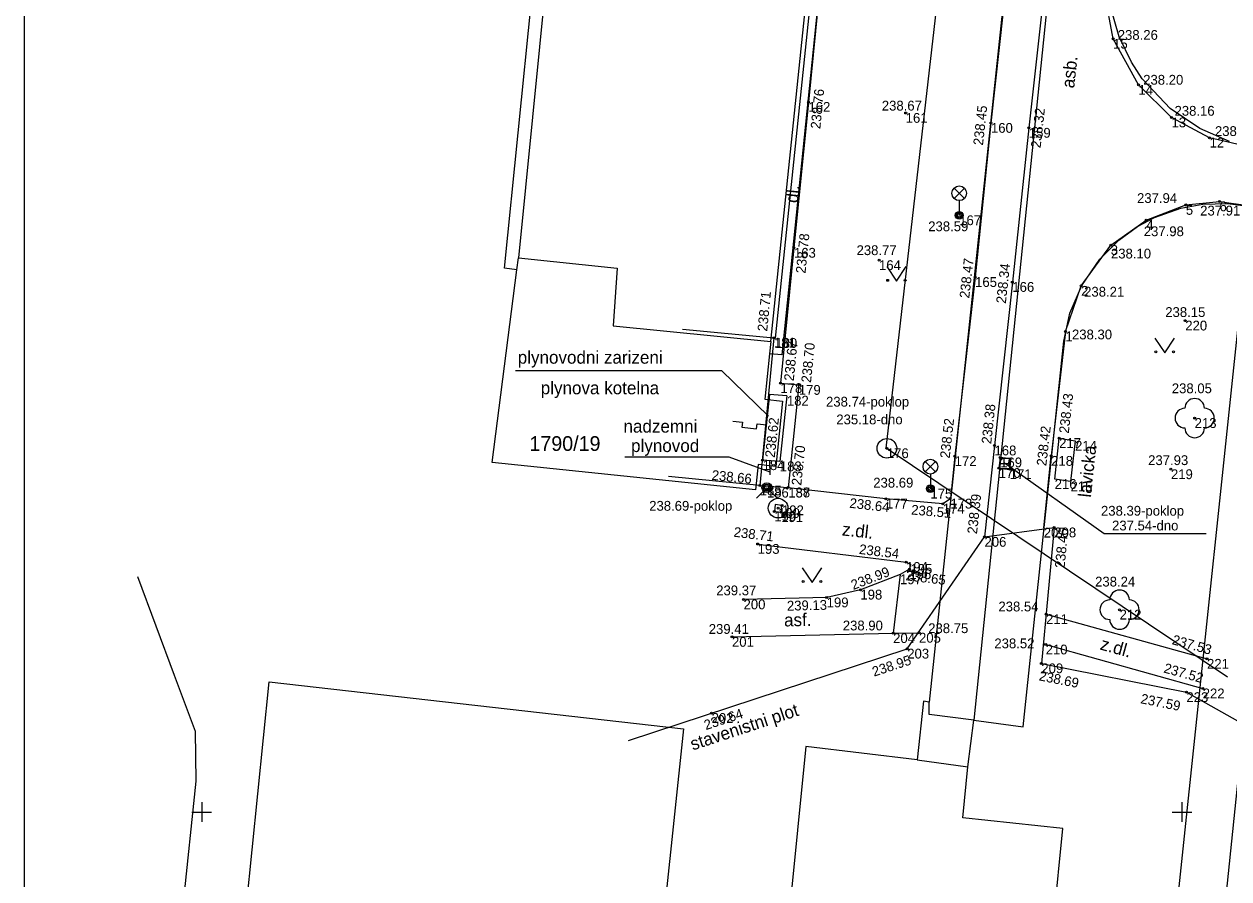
# Model space of a CAD drawing. Extents: x -596309 to -596099, y -1158697 to -1158513.
# Drawn here: x -596309.1 to -596247.6, y -1158653.4 to -1158609.8 of the extents above; entities that cross this region are included whole.
import ezdxf

# ---------------------------------------------------------------- set-up
doc = ezdxf.new("R2010")
doc.units = 0
for name, color, linetype in [('Vrstva 1', 7, 'Continuous'), ('Vrstva 10', 7, 'Continuous'), ('Vrstva 11', 7, 'Continuous'), ('Vrstva 14', 7, 'Continuous'), ('Vrstva 2', 7, 'Continuous'), ('Vrstva 22', 7, 'Continuous'), ('Vrstva 27', 7, 'Continuous'), ('Vrstva 3', 7, 'Continuous'), ('Vrstva 31', 7, 'Continuous'), ('Vrstva 32', 7, 'Continuous'), ('Vrstva 33', 7, 'Continuous'), ('Vrstva 36', 7, 'Continuous'), ('Vrstva 40', 7, 'Continuous'), ('Vrstva 5', 7, 'Continuous'), ('Vrstva 51', 7, 'Continuous'), ('Vrstva 58', 7, 'Continuous'), ('Vrstva 59', 7, 'Continuous'), ('Vrstva 60', 7, 'Continuous'), ('Vrstva 61', 7, 'Continuous'), ('Vrstva 63', 7, 'Continuous'), ('Vrstva 7', 7, 'Continuous')]:
    doc.layers.add(name, color=color, linetype=linetype)

msp = doc.modelspace()

# ---------------------------------------------------------------- linework, layer by layer
at = {"layer": 'Vrstva 1'}
for p, q in [((-596284.56, -1158622.27), (-596277.87, -1158556.03)), ((-596252.59, -1158566.74), (-596260.61, -1158645.31)), ((-596268.11, -1158604.33), (-596270.4, -1158626.69)), ((-596258.77, -1158605.41), (-596262.89, -1158644.39)), ((-596253.2, -1158610.47), (-596253.61, -1158609.06)), ((-596252.57, -1158611.75), (-596253.2, -1158610.47)), ((-596252.02, -1158612.6), (-596252.57, -1158611.75)), ((-596250.6, -1158614.12), (-596252.02, -1158612.6)), ((-596249.08, -1158615.14), (-596250.6, -1158614.12)), ((-596247.57, -1158615.8), (-596249.08, -1158615.14)), ((-596253.81, -1158688.53), (-596246.48, -1158619.11)), ((-596251.4, -1158619.68), (-596250.05, -1158619.21)), ((-596250.05, -1158619.21), (-596248.94, -1158619)), ((-596248.94, -1158619), (-596247.67, -1158618.96)), ((-596247.67, -1158618.96), (-596246.48, -1158619.11)), ((-596252.26, -1158620.14), (-596251.4, -1158619.68)), ((-596244.17, -1158619.38), (-596252.171, -1158697)), ((-596253.22, -1158620.84), (-596252.26, -1158620.14)), ((-596254.18, -1158621.8), (-596253.22, -1158620.84)), ((-596255.11, -1158623.15), (-596254.18, -1158621.8)), ((-596283.92, -1158622.34), (-596284.56, -1158622.27)), ((-596255.71, -1158624.56), (-596255.11, -1158623.15)), ((-596256.02, -1158625.99), (-596255.71, -1158624.56)), ((-596258.09, -1158645.65), (-596256.02, -1158625.99)), ((-596270.4, -1158626.69), (-596271.03, -1158626.63)), ((-596303.27, -1158637.985), (-596301.41, -1158643.02)), ((-596301.41, -1158643.02), (-596300.34, -1158645.87)), ((-596300.63, -1158683.35), (-596296.56, -1158643.35)), ((-596296.56, -1158643.35), (-596275.42, -1158645.75)), ((-596275.42, -1158645.75), (-596279.26, -1158682.13)), ((-596260.61, -1158645.31), (-596258.09, -1158645.65)), ((-596300.34, -1158645.87), (-596300.3, -1158648.42)), ((-596263.5, -1158647.34), (-596260.92, -1158647.69)), ((-596300.3, -1158648.42), (-596303.27, -1158677.086))]:
    msp.add_line(p, q, dxfattribs=at)
for points in [[(-596270.97, -1158626.01), (-596268.7, -1158604.18), (-596268.05, -1158598.2), (-596264.37, -1158561.26), (-596268.27, -1158560.79), (-596268.03, -1158558.14), (-596277.39, -1158556.98), (-596283.84, -1158621.73)], [(-596270.97, -1158626.01), (-596271.03, -1158626.63), (-596271.27, -1158628.94), (-596270.38, -1158629.04), (-596270.72, -1158632.37), (-596271.62, -1158632.28), (-596271.75, -1158633.57), (-596285.18, -1158632.17), (-596283.92, -1158622.34), (-596283.84, -1158621.73)], [(-596283.84, -1158621.73), (-596278.81, -1158622.27), (-596279.01, -1158625.2), (-596270.97, -1158626.01)], [(-596260.653, -1158697), (-596259.75, -1158687.83), (-596256.08, -1158650.83), (-596261.18, -1158650.29), (-596260.92, -1158647.69), (-596260.61, -1158645.31), (-596262.9, -1158645.02), (-596262.89, -1158644.39), (-596263.19, -1158644.35), (-596263.5, -1158647.34)], [(-596263.5, -1158647.34), (-596269.19, -1158646.65), (-596274.198, -1158697)]]:
    msp.add_lwpolyline(points, dxfattribs=at)
at = {"layer": 'Vrstva 10'}
for p in [(-596255.94, -1158625.49), (-596257.05, -1158635.5)]:
    msp.add_line(p, (-596256.67, -1158631.84), dxfattribs=at)
for points in [[(-596255.23, -1158545.06), (-596254.2, -1158547.01), (-596253.17, -1158550.76), (-596252.36, -1158555.01), (-596251.99, -1158558.97), (-596251.94, -1158561.36), (-596252.44, -1158566.04), (-596253.24, -1158573.57), (-596254.4, -1158584.31), (-596255.5, -1158594.13), (-596256.77, -1158605.75), (-596257.81, -1158615.11), (-596258.65, -1158622.97), (-596259.56, -1158631.31), (-596260.07, -1158635.97)], [(-596255.94, -1158625.49), (-596255.14, -1158623.17), (-596253.63, -1158621.09), (-596251.82, -1158619.81), (-596249.8, -1158619.04), (-596248.08, -1158618.86), (-596246.63, -1158619.07), (-596246.32, -1158616.14), (-596248.59, -1158615.61), (-596250.53, -1158614.58), (-596252.22, -1158612.92), (-596253.51, -1158610.57), (-596253.93, -1158608.27)]]:
    msp.add_lwpolyline(points, dxfattribs=at)
at = {"layer": 'Vrstva 11'}
for p, q in [((-596271.53, -1158633.35), (-596270.08, -1158633.45)), ((-596264.38, -1158637.88), (-596264.73, -1158640.88)), ((-596256.93, -1158639.91), (-596248.72, -1158642.19)), ((-596256.95, -1158641.46), (-596248.94, -1158643.7))]:
    msp.add_line(p, q, dxfattribs=at)
for points in [[(-596268.09, -1158604.13), (-596269.05, -1158613.79), (-596269.79, -1158621.23), (-596270.48, -1158628.13), (-596269.54, -1158628.22), (-596270.08, -1158633.46)], [(-596268.09, -1158604.13), (-596264.04, -1158604.57), (-596258.68, -1158605.13), (-596259.74, -1158614.86), (-596260.55, -1158622.72), (-596261.59, -1158631.85), (-596261.81, -1158634.02), (-596262.2, -1158634.28), (-596265.1, -1158634.02), (-596270.08, -1158633.46)], [(-596271.64, -1158636.33), (-596264.07, -1158637.25), (-596263.85, -1158637.35), (-596263.9, -1158637.62), (-596264.38, -1158637.88), (-596266.4, -1158638.66), (-596268.12, -1158639.06), (-596272.36, -1158639.16)], [(-596272.95, -1158641.07), (-596264.73, -1158640.88), (-596263.41, -1158640.86)]]:
    msp.add_lwpolyline(points, dxfattribs=at)
msp.add_lwpolyline([(-596255.45, -1158631.07), (-596255.68, -1158633.14), (-596256.49, -1158633.02), (-596256.26, -1158630.93)], close=True, dxfattribs=at)
at = {"layer": 'Vrstva 2'}
msp.add_lwpolyline([(-596248.77, -1158635.814), (-596253.967, -1158635.814), (-596259.048, -1158632.215)], dxfattribs=at)
for centre in [(-596253.51, -1158610.57), (-596252.22, -1158612.92), (-596269.05, -1158613.79), (-596264.09, -1158614.35), (-596259.74, -1158614.86), (-596250.53, -1158614.58), (-596257.81, -1158615.11), (-596248.59, -1158615.61), (-596249.8, -1158619.04), (-596248.08, -1158618.86), (-596251.82, -1158619.81), (-596269.79, -1158621.23), (-596253.63, -1158621.09), (-596265.45, -1158621.86), (-596260.55, -1158622.72), (-596258.65, -1158622.97), (-596255.14, -1158623.17), (-596249.83, -1158624.94), (-596255.94, -1158625.49), (-596270.81, -1158625.81), (-596270.48, -1158628.13), (-596269.54, -1158628.22), (-596249.35, -1158629.91), (-596256.26, -1158630.93), (-596265.05, -1158631.45), (-596259.56, -1158631.31), (-596271.39, -1158632.06), (-596261.59, -1158631.85), (-596259.27, -1158631.92), (-596256.67, -1158631.84), (-596259.34, -1158632.46), (-596258.78, -1158632.52), (-596250.56, -1158632.52), (-596271.53, -1158633.35), (-596270.08, -1158633.45), (-596265.1, -1158634.02), (-596270.79, -1158634.67), (-596270.6, -1158634.5), (-596270.44, -1158634.71), (-596270.4, -1158634.36), (-596262.2, -1158634.28), (-596260.07, -1158635.97), (-596256.51, -1158635.49), (-596271.64, -1158636.33), (-596264.07, -1158637.25), (-596263.9, -1158637.62), (-596268.12, -1158639.06), (-596266.4, -1158638.66), (-596272.36, -1158639.16), (-596253.18, -1158639.68), (-596256.93, -1158639.91), (-596264.73, -1158640.88), (-596263.41, -1158640.86), (-596272.95, -1158641.07), (-596256.95, -1158641.46), (-596264.01, -1158641.67), (-596257.17, -1158642.42), (-596248.72, -1158642.19), (-596249.77, -1158643.89), (-596248.94, -1158643.7), (-596273.99, -1158644.95)]:
    msp.add_circle(centre, 0.05, dxfattribs=at)
at = {"layer": 'Vrstva 22'}
for centre in [(-596249.35, -1158629.91), (-596253.18, -1158639.68)]:
    msp.add_circle(centre, 0.05, dxfattribs=at)
for centre, start, end in [((-596249.35, -1158629.41), 0, 180), ((-596249.85, -1158629.91), 90, 270), ((-596248.85, -1158629.91), 270, 90), ((-596249.35, -1158630.41), 180, 0), ((-596253.18, -1158639.18), 0, 180), ((-596253.68, -1158639.68), 90, 270), ((-596252.68, -1158639.68), 270, 90), ((-596253.18, -1158640.18), 180, 0)]:
    msp.add_arc(centre, 0.5, start, end, dxfattribs=at)
at = {"layer": 'Vrstva 27'}
msp.add_line((-596259.282, -1158632.221), (-596258.782, -1158632.221), dxfattribs=at)
msp.add_lwpolyline([(-596259.282, -1158632.471), (-596258.782, -1158632.471), (-596258.782, -1158631.971), (-596259.282, -1158631.971)], close=True, dxfattribs=at)
for centre in [(-596265.05, -1158631.45), (-596270.6, -1158634.5)]:
    msp.add_circle(centre, 0.5, dxfattribs=at)
at = {"layer": 'Vrstva 3'}
for p, q in [((-596253.51, -1158610.57), (-596253.509, -1158610.57)), ((-596252.22, -1158612.92), (-596252.219, -1158612.92)), ((-596269.05, -1158613.79), (-596269.049, -1158613.79)), ((-596264.09, -1158614.35), (-596264.089, -1158614.35)), ((-596259.74, -1158614.86), (-596259.739, -1158614.86)), ((-596250.53, -1158614.58), (-596250.529, -1158614.58)), ((-596257.81, -1158615.11), (-596257.809, -1158615.11)), ((-596248.59, -1158615.61), (-596248.589, -1158615.61)), ((-596249.8, -1158619.04), (-596249.799, -1158619.04)), ((-596248.08, -1158618.86), (-596248.079, -1158618.86)), ((-596261.36, -1158619.57), (-596261.359, -1158619.57)), ((-596251.82, -1158619.81), (-596251.819, -1158619.81)), ((-596253.63, -1158621.09), (-596253.629, -1158621.09)), ((-596269.79, -1158621.23), (-596269.789, -1158621.23)), ((-596265.45, -1158621.86), (-596265.449, -1158621.86)), ((-596260.55, -1158622.72), (-596260.549, -1158622.72)), ((-596258.65, -1158622.97), (-596258.649, -1158622.97)), ((-596255.14, -1158623.17), (-596255.139, -1158623.17)), ((-596255.94, -1158625.49), (-596255.939, -1158625.49)), ((-596249.83, -1158624.94), (-596249.829, -1158624.94)), ((-596270.81, -1158625.81), (-596270.809, -1158625.81)), ((-596270.74, -1158625.83), (-596270.739, -1158625.83)), ((-596270.48, -1158628.13), (-596270.479, -1158628.13)), ((-596269.54, -1158628.22), (-596269.539, -1158628.22)), ((-596270.15, -1158628.77), (-596270.149, -1158628.77)), ((-596249.35, -1158629.91), (-596249.349, -1158629.91)), ((-596256.26, -1158630.93), (-596256.259, -1158630.93)), ((-596265.05, -1158631.45), (-596265.049, -1158631.45)), ((-596259.56, -1158631.31), (-596259.559, -1158631.31)), ((-596255.45, -1158631.07), (-596255.449, -1158631.07)), ((-596271.39, -1158632.06), (-596271.389, -1158632.06)), ((-596270.51, -1158632.12), (-596270.509, -1158632.12)), ((-596261.59, -1158631.85), (-596261.589, -1158631.85)), ((-596259.27, -1158631.92), (-596259.269, -1158631.92)), ((-596256.67, -1158631.84), (-596256.669, -1158631.84)), ((-596259.34, -1158632.46), (-596259.339, -1158632.46)), ((-596258.78, -1158632.52), (-596258.779, -1158632.52)), ((-596250.56, -1158632.52), (-596250.559, -1158632.52)), ((-596271.53, -1158633.35), (-596271.529, -1158633.35)), ((-596271.17, -1158633.46), (-596271.169, -1158633.46)), ((-596270.08, -1158633.45), (-596270.079, -1158633.45)), ((-596270.08, -1158633.46), (-596270.079, -1158633.46)), ((-596256.49, -1158633.02), (-596256.489, -1158633.02)), ((-596255.68, -1158633.14), (-596255.679, -1158633.14)), ((-596265.1, -1158634.02), (-596265.099, -1158634.02)), ((-596262.83, -1158633.51), (-596262.829, -1158633.51)), ((-596261.81, -1158634.02), (-596261.809, -1158634.02)), ((-596270.79, -1158634.67), (-596270.789, -1158634.67)), ((-596270.6, -1158634.5), (-596270.599, -1158634.5)), ((-596270.44, -1158634.71), (-596270.439, -1158634.71)), ((-596270.4, -1158634.36), (-596270.399, -1158634.36)), ((-596262.2, -1158634.28), (-596262.199, -1158634.28)), ((-596257.05, -1158635.5), (-596257.049, -1158635.5)), ((-596256.51, -1158635.49), (-596256.509, -1158635.49)), ((-596271.64, -1158636.33), (-596271.639, -1158636.33)), ((-596260.07, -1158635.97), (-596260.069, -1158635.97)), ((-596264.07, -1158637.25), (-596264.069, -1158637.25)), ((-596263.9, -1158637.62), (-596263.899, -1158637.62)), ((-596263.85, -1158637.35), (-596263.849, -1158637.35)), ((-596264.38, -1158637.88), (-596264.379, -1158637.88)), ((-596266.4, -1158638.66), (-596266.399, -1158638.66)), ((-596272.36, -1158639.16), (-596272.359, -1158639.16)), ((-596268.12, -1158639.06), (-596268.119, -1158639.06)), ((-596256.93, -1158639.91), (-596256.929, -1158639.91)), ((-596253.18, -1158639.68), (-596253.179, -1158639.68)), ((-596263.41, -1158640.86), (-596263.409, -1158640.86)), ((-596272.95, -1158641.07), (-596272.949, -1158641.07)), ((-596264.73, -1158640.88), (-596264.729, -1158640.88)), ((-596256.95, -1158641.46), (-596256.949, -1158641.46)), ((-596264.01, -1158641.67), (-596264.009, -1158641.67)), ((-596257.17, -1158642.42), (-596257.169, -1158642.42)), ((-596248.72, -1158642.19), (-596248.719, -1158642.19)), ((-596249.77, -1158643.89), (-596249.769, -1158643.89)), ((-596248.94, -1158643.7), (-596248.939, -1158643.7)), ((-596273.99, -1158644.95), (-596273.989, -1158644.95))]:
    msp.add_line(p, q, dxfattribs=at)
at = {"layer": 'Vrstva 31'}
msp.add_lwpolyline([(-596271.7, -1158633.99), (-596271.17, -1158633.46), (-596270.64, -1158633.99)], dxfattribs=at)
for radius in [0.25, 0.18, 0.11]:
    msp.add_circle((-596271.17, -1158633.46), radius, dxfattribs=at)
at = {"layer": 'Vrstva 32'}
msp.add_lwpolyline([(-596272.911, -1158630.069), (-596272.414, -1158630.122), (-596272.44, -1158630.371), (-596271.695, -1158630.451), (-596271.668, -1158630.203), (-596271.171, -1158630.256)], dxfattribs=at)
at = {"layer": 'Vrstva 33'}
for p, q in [((-596261.625, -1158618.71), (-596261.095, -1158618.18)), ((-596261.625, -1158618.18), (-596261.095, -1158618.71)), ((-596261.36, -1158618.82), (-596261.36, -1158619.57)), ((-596263.095, -1158632.65), (-596262.565, -1158632.12)), ((-596263.095, -1158632.12), (-596262.565, -1158632.65)), ((-596262.83, -1158632.76), (-596262.83, -1158633.51))]:
    msp.add_line(p, q, dxfattribs=at)
for centre, radius in [((-596261.36, -1158618.445), 0.375), ((-596261.36, -1158619.57), 0.2), ((-596261.36, -1158619.57), 0.145), ((-596261.36, -1158619.57), 0.0876), ((-596262.83, -1158632.385), 0.375), ((-596262.83, -1158633.51), 0.2), ((-596262.83, -1158633.51), 0.145), ((-596262.83, -1158633.51), 0.0876)]:
    msp.add_circle(centre, radius, dxfattribs=at)
at = {"layer": 'Vrstva 36'}
for points in [[(-596265.059, -1158622.184), (-596264.559, -1158622.934), (-596264.059, -1158622.184)], [(-596251.378, -1158625.832), (-596250.878, -1158626.582), (-596250.378, -1158625.832)], [(-596269.365, -1158637.543), (-596268.865, -1158638.293), (-596268.365, -1158637.543)]]:
    msp.add_lwpolyline(points, dxfattribs=at)
for centre in [(-596265.009, -1158622.884), (-596264.11, -1158622.884), (-596251.328, -1158626.532), (-596250.428, -1158626.532), (-596269.315, -1158638.243), (-596268.416, -1158638.243)]:
    msp.add_circle(centre, 0.05, dxfattribs=at)
at = {"layer": 'Vrstva 40'}
for points in [[(-596284, -1158627.481), (-596273.478, -1158627.481), (-596271.091, -1158629.811)], [(-596278.411, -1158631.881), (-596273.109, -1158631.881), (-596271.022, -1158632.653)]]:
    msp.add_lwpolyline(points, dxfattribs=at)
at = {"layer": 'Vrstva 5'}
msp.add_line((-596275.47, -1158625.365), (-596270.81, -1158625.81), dxfattribs=at)
msp.add_lwpolyline([(-596269.438, -1158560.623), (-596264.12, -1158561.11), (-596267.89, -1158598.35), (-596269.33, -1158598.167), (-596269.72, -1158601.59), (-596269.95, -1158603.92), (-596268.48, -1158604.11), (-596270.74, -1158625.83), (-596270.81, -1158625.81), (-596271.53, -1158633.35), (-596276.188, -1158632.886)], dxfattribs=at)
at = {"layer": 'Vrstva 51'}
for points in [[(-596270.15, -1158628.77), (-596271.03, -1158628.71), (-596271.39, -1158632.06)], [(-596270.15, -1158628.77), (-596270.51, -1158632.12), (-596271.39, -1158632.06)]]:
    msp.add_lwpolyline(points, dxfattribs=at)
at = {"layer": 'Vrstva 58'}
for points in [[(-596259.27, -1158631.92), (-596259.34, -1158632.46), (-596258.782, -1158632.532), (-596258.712, -1158631.992)], [(-596270.79, -1158634.67), (-596270.44, -1158634.71), (-596270.4, -1158634.36), (-596270.75, -1158634.32)]]:
    msp.add_lwpolyline(points, close=True, dxfattribs=at)
at = {"layer": 'Vrstva 60'}
msp.add_line((-596271.01, -1158632.81), (-596271.02, -1158632.085), dxfattribs=at)
msp.add_lwpolyline([(-596247.668, -1158643.114), (-596265.091, -1158631.45), (-596260.921, -1158595.1), (-596258.491, -1158561.83), (-596276.3, -1158553.438)], dxfattribs=at)
at = {"layer": 'Vrstva 61'}
for p, q in [((-596300.5, -1158650), (-596299.5, -1158650)), ((-596300, -1158649.5), (-596300, -1158650.5)), ((-596250.5, -1158650), (-596249.5, -1158650)), ((-596250, -1158649.5), (-596250, -1158650.5))]:
    msp.add_line(p, q, dxfattribs=at)
at = {"layer": 'Vrstva 63'}
msp.add_lwpolyline([(-596309.058, -1158687.689), (-596099.058, -1158687.689), (-596099.058, -1158539.189), (-596309.058, -1158539.189)], close=True, dxfattribs=at)
at = {"layer": 'Vrstva 7'}
msp.add_lwpolyline([(-596278.232, -1158646.344), (-596264.01, -1158641.67), (-596260.07, -1158635.97), (-596256.51, -1158635.49), (-596257.17, -1158642.42), (-596249.77, -1158643.89), (-596245.93, -1158646.05), (-596242.41, -1158660.16), (-596237.69, -1158668.9), (-596235.01, -1158671.41), (-596218.43, -1158672.96), (-596214.81, -1158675.09)], dxfattribs=at)

# ---------------------------------------------------------------- texts
at = {"layer": 'Vrstva 14'}
msp.add_text('1790/19', height=0.75, dxfattribs=at).set_placement((-596283.283, -1158631.58))
at = {"layer": 'Vrstva 2'}
for s, p in [('238.26', (-596253.272, -1158610.617)), ('238.20', (-596251.975, -1158612.906)), ('238.67', (-596265.308, -1158614.225)), ('238.16', (-596250.377, -1158614.489)), ('238.09', (-596248.315, -1158615.523)), ('237.94', (-596252.289, -1158618.939)), ('237.91', (-596249.069, -1158619.577)), ('238.59', (-596262.941, -1158620.378)), ('237.98', (-596251.945, -1158620.63)), ('238.77', (-596266.597, -1158621.596)), ('238.10', (-596253.619, -1158621.768)), ('238.21', (-596254.988, -1158623.714)), ('238.15', (-596250.85, -1158624.752)), ('238.30', (-596255.608, -1158625.894)), ('238.05', (-596250.516, -1158628.64)), ('238.74-poklop', (-596268.153, -1158629.323)), ('235.18-dno', (-596267.629, -1158630.227)), ('237.93', (-596251.723, -1158632.304)), ('238.69', (-596265.744, -1158633.452)), ('238.69-poklop', (-596277.173, -1158634.633)), ('238.39-poklop', (-596254.128, -1158634.885)), ('237.54-dno', (-596253.564, -1158635.637)), ('238.24', (-596254.428, -1158638.497)), ('239.37', (-596273.754, -1158638.946)), ('238.54', (-596259.36, -1158639.766)), ('238.90', (-596267.298, -1158640.736)), ('239.41', (-596274.136, -1158640.913)), ('238.75', (-596262.942, -1158640.874)), ('238.52', (-596259.567, -1158641.648))]:
    msp.add_text(s, height=0.5, dxfattribs=at).set_placement(p)
for s, rotation, p in [('238.76', 84.31991, (-596268.446, -1158615.179)), ('238.45', 83.78264, (-596260.15, -1158616.023)), ('238.32', 83.65981, (-596257.211, -1158616.158)), ('238.78', 84.28941, (-596269.202, -1158622.55)), ('238.47', 83.50144, (-596260.851, -1158623.82)), ('238.34', 83.77294, (-596258.983, -1158624.085)), ('238.71', 84.54532, (-596271.155, -1158625.505)), ('238.67', 84.28941, (-596269.802, -1158628.035)), ('238.70', 84.28941, (-596268.922, -1158628.125)), ('238.43', 83.44203, (-596255.774, -1158630.709)), ('238.38', 83.77294, (-596259.729, -1158631.248)), ('238.62', 83.86638, (-596270.771, -1158631.942)), ('238.52', 83.50144, (-596261.849, -1158631.981)), ('238.42', 83.44203, (-596256.92, -1158632.37)), ('238.70', 84.11624, (-596269.417, -1158633.365)), ('238.66', 354.3102, (-596274.002, -1158633.055)), ('238.64', 353.58405, (-596266.977, -1158634.478)), ('238.39', 83.75429, (-596260.456, -1158635.838)), ('238.51', 354.87683, (-596263.826, -1158634.821)), ('238.71', 353.07069, (-596272.885, -1158635.954)), ('238.46', 84.55967, (-596255.987, -1158637.583)), ('238.54', 353.07069, (-596266.487, -1158636.832)), ('238.99', 21.1135, (-596266.765, -1158638.677)), ('238.65', 353.07069, (-596264.11, -1158638.174)), ('239.13', 1.35107, (-596270.142, -1158639.731)), ('237.53', 344.37633, (-596250.538, -1158641.43)), ('238.95', 18.19349, (-596265.705, -1158643.095)), ('237.52', 344.37633, (-596250.963, -1158642.874)), ('238.69', 348.76454, (-596257.32, -1158643.278)), ('237.59', 348.76454, (-596252.137, -1158644.446)), ('239.64', 18.19349, (-596274.282, -1158645.822))]:
    msp.add_text(s, height=0.5, rotation=rotation, dxfattribs=at).set_placement(p)
at = {"layer": 'Vrstva 40'}
for s, rotation, p in [('asb.', 83.65981, (-596255.498, -1158613.106)), ('dl.', 84.15391, (-596269.592, -1158618.959)), ('lavicka', 84.0725, (-596254.641, -1158633.976)), ('z.dl.', 353.58405, (-596267.364, -1158635.889)), ('asf.', 1.32412, (-596270.288, -1158640.536)), ('z.dl.', 344.47949, (-596254.217, -1158641.702)), ('stavenistni plot', 18.19349, (-596274.954, -1158646.862))]:
    msp.add_text(s, height=0.65, rotation=rotation, dxfattribs=at).set_placement(p)
for s, p in [('plynovodni zarizeni', (-596283.879, -1158627.134)), ('plynova kotelna', (-596282.706, -1158628.693)), ('nadzemni', (-596278.485, -1158630.649)), ('plynovod', (-596278.099, -1158631.639))]:
    msp.add_text(s, height=0.65, dxfattribs=at).set_placement(p)
at = {"layer": 'Vrstva 59'}
for s, p in [('15', (-596253.51, -1158611.07)), ('14', (-596252.22, -1158613.42)), ('162', (-596269.05, -1158614.29)), ('161', (-596264.09, -1158614.85)), ('160', (-596259.74, -1158615.36)), ('13', (-596250.53, -1158615.08)), ('159', (-596257.81, -1158615.61)), ('12', (-596248.59, -1158616.11)), ('5', (-596249.8, -1158619.54)), ('6', (-596248.08, -1158619.36)), ('167', (-596261.36, -1158620.07)), ('4', (-596251.82, -1158620.31)), ('3', (-596253.63, -1158621.59)), ('163', (-596269.79, -1158621.73)), ('164', (-596265.45, -1158622.36)), ('165', (-596260.55, -1158623.22)), ('166', (-596258.65, -1158623.47)), ('2', (-596255.14, -1158623.67)), ('1', (-596255.94, -1158625.99)), ('220', (-596249.83, -1158625.44)), ('181', (-596270.81, -1158626.31)), ('180', (-596270.74, -1158626.33)), ('178', (-596270.48, -1158628.63)), ('179', (-596269.54, -1158628.72)), ('182', (-596270.15, -1158629.27)), ('213', (-596249.35, -1158630.41)), ('217', (-596256.26, -1158631.43)), ('176', (-596265.05, -1158631.95)), ('168', (-596259.56, -1158631.81)), ('214', (-596255.45, -1158631.57)), ('184', (-596271.39, -1158632.56)), ('183', (-596270.51, -1158632.62)), ('172', (-596261.59, -1158632.35)), ('169', (-596259.27, -1158632.42)), ('218', (-596256.67, -1158632.34)), ('170', (-596259.34, -1158632.96)), ('171', (-596258.78, -1158633.02)), ('219', (-596250.56, -1158633.02)), ('185', (-596271.53, -1158633.85)), ('186', (-596271.17, -1158633.96)), ('188', (-596270.08, -1158633.95)), ('187', (-596270.08, -1158633.96)), ('216', (-596256.49, -1158633.52)), ('215', (-596255.68, -1158633.64)), ('177', (-596265.1, -1158634.52)), ('175', (-596262.83, -1158634.01)), ('173', (-596261.81, -1158634.52)), ('190', (-596270.79, -1158635.17)), ('189', (-596270.6, -1158635)), ('191', (-596270.44, -1158635.21)), ('192', (-596270.4, -1158634.86)), ('174', (-596262.2, -1158634.78)), ('207', (-596257.05, -1158636)), ('208', (-596256.51, -1158635.99)), ('193', (-596271.64, -1158636.83)), ('206', (-596260.07, -1158636.47)), ('194', (-596264.07, -1158637.75)), ('196', (-596263.9, -1158638.12)), ('195', (-596263.85, -1158637.85)), ('197', (-596264.38, -1158638.38)), ('198', (-596266.4, -1158639.16)), ('200', (-596272.36, -1158639.66)), ('199', (-596268.12, -1158639.56)), ('211', (-596256.93, -1158640.41)), ('212', (-596253.18, -1158640.18)), ('205', (-596263.41, -1158641.36)), ('201', (-596272.95, -1158641.57)), ('204', (-596264.73, -1158641.38)), ('210', (-596256.95, -1158641.96)), ('203', (-596264.01, -1158642.17)), ('209', (-596257.17, -1158642.92)), ('221', (-596248.72, -1158642.69)), ('223', (-596249.77, -1158644.39)), ('222', (-596248.94, -1158644.2)), ('202', (-596273.99, -1158645.45))]:
    msp.add_text(s, height=0.5, dxfattribs=at).set_placement(p)

doc.saveas('drawing.dxf')
